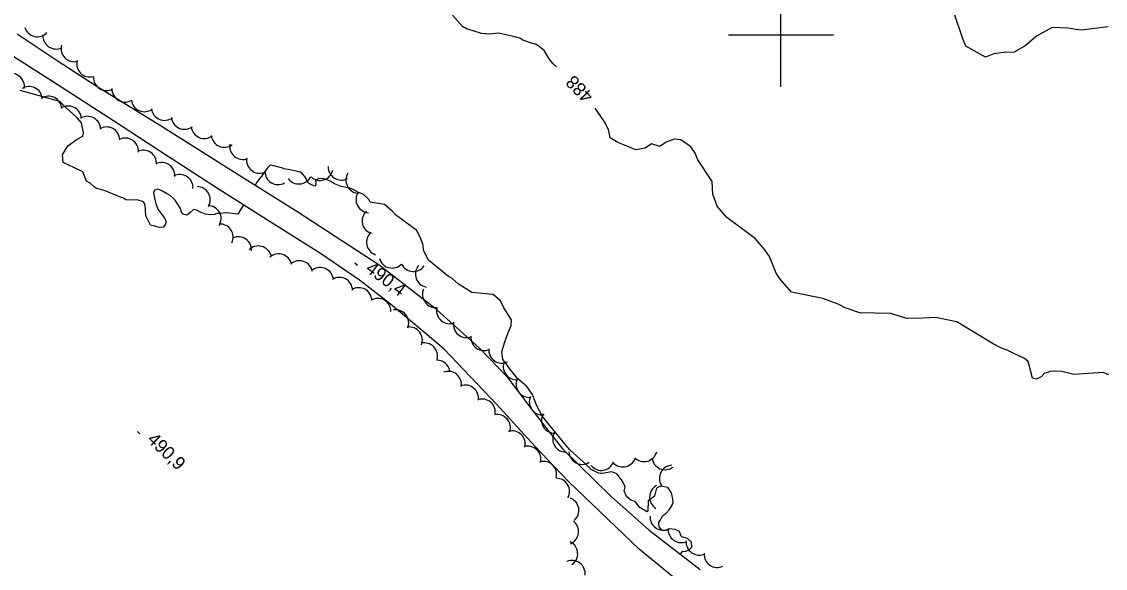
# Model space of a CAD drawing. Extents: x 642515 to 647219, y 6080136 to 6084356.
# Drawn here: x 643026.5 to 643274.3, y 6082078.2 to 6082203 of the extents above; entities that cross this region are included whole.
import ezdxf

# ---------------------------------------------------------------- set-up
doc = ezdxf.new("R2010")
doc.units = 0
for name, color, linetype in [('Level 1', 7, 'Continuous'), ('Level 2', 7, 'Continuous'), ('Level 21', 7, 'Continuous'), ('Level 3', 7, 'Continuous'), ('Level 44', 7, 'Continuous'), ('Level 61', 7, 'Continuous')]:
    doc.layers.add(name, color=color, linetype=linetype)

msp = doc.modelspace()

# ---------------------------------------------------------------- linework, layer by layer
at = {"layer": 'Level 1'}
for points in [[(643063.32, 6082159.04), (643063.05, 6082159.59), (643062.79, 6082160.5), (643062.3, 6082161.23), (643061.67, 6082162.24), (643060.73, 6082163.16), (643059.65, 6082163.82), (643058.73, 6082164.33), (643057.82, 6082164.76), (643056.94, 6082164.54), (643056.69, 6082164), (643056.82, 6082163.21), (643056.95, 6082162.41), (643057.25, 6082161.54), (643057.41, 6082160.86), (643057.65, 6082160.19), (643059.31, 6082158.11), (643059.6, 6082157.33), (643059.32, 6082156.66), (643058.91, 6082156.12), (643057.95, 6082156.06), (643056.97, 6082156.32), (643056.03, 6082156.55), (643054.93, 6082158.66), (643054.89, 6082159.99), (643054.77, 6082161.23), (643054.37, 6082161.89), (643052.93, 6082162.33), (643051.37, 6082162.28), (643050.36, 6082162.34), (643049.81, 6082162.75), (643048.94, 6082163.06), (643048.2, 6082163.34), (643046.55, 6082164.05), (643045.64, 6082164.4), (643044.57, 6082164.74), (643043.63, 6082164.96), (643043.17, 6082165.22), (643042.23, 6082166.13), (643041.39, 6082166.64), (643040.5, 6082168.73), (643038.59, 6082169.66), (643036.02, 6082170.88), (643035.91, 6082172.65), (643037.07, 6082174.65), (643039.23, 6082176.23), (643040.56, 6082176.87), (643040.67, 6082177.68), (643040.21, 6082179.91), (643039.17, 6082181.14), (643038.23, 6082181.97), (643036.62, 6082183.41), (643035.24, 6082184.78), (643026.23, 6082187.31)], [(643172.61, 6082096.95), (643171.71, 6082096.45), (643171.18, 6082094.65), (643170.49, 6082094.04), (643169.8, 6082093.6), (643169.7, 6082091.25), (643169.51, 6082091.04), (643167.88, 6082092.03), (643166.83, 6082093.42), (643165.84, 6082093.76), (643164.79, 6082094.55), (643164.3, 6082095.89), (643164.53, 6082096.75), (643163.93, 6082098.04), (643162.62, 6082099.74), (643161.5, 6082100.19), (643159.27, 6082099.82), (643158.95, 6082099.8), (643158.38, 6082099.93), (643156.76, 6082100.76), (643155.69, 6082101.78), (643154.11, 6082103.18), (643151.89, 6082105.22), (643150.37, 6082107.03), (643145.59, 6082112.87), (643144.22, 6082115.45), (643143.34, 6082117.89), (643142.03, 6082119.67), (643139.9, 6082121.56), (643138.07, 6082123.78), (643137.27, 6082124.95), (643136.57, 6082125.87), (643136.3, 6082127.63), (643136.9, 6082129.68), (643137.8, 6082132.07), (643138.43, 6082133.64), (643138.51, 6082134.93), (643136.81, 6082137.65), (643135.98, 6082139.3), (643134.37, 6082140.73), (643129.43, 6082141.16), (643126.33, 6082143.16), (643124.97, 6082144.36), (643124.14, 6082144.8), (643119.56, 6082148.56), (643118.47, 6082150.59), (643118.28, 6082152.27), (643117.81, 6082153.45), (643116.88, 6082155.33), (643111.99, 6082158.91), (643111.3, 6082159.67), (643109.52, 6082161.26), (643106.18, 6082161.78), (643105.9, 6082162.41), (643104.58, 6082163.66), (643103.55, 6082164.05), (643102.47, 6082164.63), (643101.56, 6082164.98), (643100.74, 6082165.17), (643099.6, 6082165.42), (643098.04, 6082165.98), (643097.24, 6082166.53), (643096.41, 6082166.89), (643095.59, 6082167.16), (643094.45, 6082167.25), (643093.71, 6082166.85), (643093.79, 6082166.33), (643093.82, 6082165.77), (643093.6, 6082165.43), (643092.82, 6082165.75), (643092.15, 6082166.19), (643091.48, 6082167.24), (643091.47, 6082167.4), (643090.77, 6082168.32), (643090.18, 6082168.69), (643089.57, 6082168.78), (643087.53, 6082169.3), (643086.43, 6082169.44), (643086.22, 6082169.55), (643084.17, 6082170.15), (643083.32, 6082170.3), (643082.79, 6082169.7), (643082.12, 6082168.78), (643081.46, 6082167.85), (643081.12, 6082167.47), (643080.97, 6082167.3), (643080.3, 6082166.37), (643079.91, 6082165.71)], [(643077.22, 6082161.19), (643075.96, 6082159.06), (643073.44, 6082159.4), (643071.6, 6082159.21), (643071.16, 6082159.22), (643070.57, 6082158.98), (643069.61, 6082158.93), (643068.47, 6082159.1), (643068.31, 6082159.17), (643067.56, 6082159.45), (643066.52, 6082159.99), (643065.79, 6082160.11), (643064.99, 6082159.38), (643064.34, 6082158.82), (643063.32, 6082159.04)], [(643177.2, 6082081.32), (643177.19, 6082081.42), (643177.67, 6082082.06), (643178.24, 6082082.01), (643179.18, 6082082.39), (643179.74, 6082083.03), (643179.64, 6082084.11), (643178.78, 6082084.94), (643177.47, 6082085.35), (643177.34, 6082085.54), (643176.95, 6082086.57), (643175.92, 6082087.03), (643174.62, 6082087.19), (643173.92, 6082086.83), (643172.91, 6082086.89), (643172.3, 6082087.66), (643172.24, 6082088.62), (643172.41, 6082089), (643173.1, 6082090.21), (643173.84, 6082090.69), (643174.63, 6082091.59), (643175.36, 6082092.76), (643175.35, 6082092.84), (643175.45, 6082093.21), (643175.44, 6082094.05), (643175.12, 6082095.4), (643174.28, 6082096.6), (643172.61, 6082096.95)]]:
    msp.add_lwpolyline(points, dxfattribs=at)
at = {"layer": 'Level 2'}
for points in [[(643148.85, 6082192.71), (643148.06, 6082193.41), (643147.1, 6082194.57), (643146.01, 6082196.44), (643144.83, 6082197.34), (643143.99, 6082197.93), (643143.58, 6082197.99), (643141.11, 6082198.81), (643140.44, 6082199.26), (643138.97, 6082199.65), (643135.53, 6082200.42), (643133.53, 6082200.22), (643131.67, 6082200.35), (643129.78, 6082200.96), (643128.22, 6082201.44), (643127.3, 6082201.95), (643125.04, 6082204.56)], [(643274.91, 6082201.88), (643271.38, 6082201.38), (643268.65, 6082201.07), (643265.72, 6082201.56), (643262.15, 6082201.7), (643258.55, 6082199.74), (643255.93, 6082197.52), (643253.43, 6082196.11), (643251.17, 6082195.99), (643248.76, 6082195.7), (643246.87, 6082194.96), (643242.36, 6082197.45), (643241.61, 6082199.34), (643239.85, 6082204.53)], [(643213.18, 6082138.53), (643209.72, 6082139.78), (643202.53, 6082141.28), (643199.94, 6082144.2), (643199.04, 6082145.6), (643197.52, 6082149.38), (643196.46, 6082150.93), (643194.2, 6082153.54), (643190.15, 6082156.53), (643187.78, 6082158.32), (643185.52, 6082160.93), (643184.55, 6082163.62), (643184.37, 6082166.51), (643181.16, 6082171.49), (643180.51, 6082172.98), (643179.53, 6082174.46), (643177.26, 6082176.02), (643175.72, 6082176.17), (643173.9, 6082175.5), (643172.43, 6082174.52), (643170.54, 6082175.14), (643169.07, 6082174.16), (643166.92, 6082173.79), (643164.35, 6082174.85), (643162.87, 6082175.41), (643161.11, 6082176.51), (643160.67, 6082178.42), (643159.76, 6082180.14), (643157.68, 6082183.31)], [(643275.09, 6082122.34), (643273.76, 6082122.9), (643267.1, 6082122.45), (643264.32, 6082123.09), (643262.62, 6082123.23), (643261.58, 6082123.09), (643261.11, 6082122.9), (643260.39, 6082122.78), (643259.64, 6082121.93), (643258.55, 6082121.38), (643257.65, 6082121.57), (643256.61, 6082125.38), (643255.84, 6082126.06), (643254.68, 6082126.63), (643252.77, 6082127.57), (643252.02, 6082127.93), (643250.54, 6082128.49), (643248.63, 6082129.42), (643247.87, 6082129.94), (643240.34, 6082134.5), (643235.44, 6082135.5), (643232.55, 6082135.32), (643228.85, 6082135.26), (643225.24, 6082136.34), (643221.69, 6082136.45), (643218.13, 6082136.56), (643214.84, 6082137.66), (643213.18, 6082138.53)]]:
    msp.add_lwpolyline(points, dxfattribs=at)
at = {"layer": 'Level 21'}
for points in [[(643175.36, 6082076.3), (643167.69, 6082082.55), (643151.53, 6082097.98), (643143.84, 6082106.08), (643135.08, 6082115.64), (643123.17, 6082128.23), (643115.92, 6082134.34), (643110.83, 6082138.54), (643103.74, 6082143.98), (643094.84, 6082150.11), (643082.74, 6082157.71), (643071.11, 6082165.05), (643059.45, 6082172.63), (643047.51, 6082180.4), (643033.59, 6082189.37), (643018.39, 6082199.03)], [(643025.49, 6082200.3), (643034.64, 6082194.18), (643043.61, 6082188.36), (643058.08, 6082179.5), (643074.33, 6082169.21), (643089.65, 6082159.6), (643108.26, 6082147.53), (643120.68, 6082137.91), (643131.24, 6082128.42), (643137.42, 6082122.04), (643143.64, 6082113.81), (643150.18, 6082105.44), (643161.4, 6082094.46), (643170, 6082086.85), (643181.65, 6082077.9)]]:
    msp.add_lwpolyline(points, dxfattribs=at)
at = {"layer": 'Level 3'}
for p, q in [((643102.69, 6082147.93), (643103.33, 6082147.44)), ((643053.01, 6082109.42), (643053.58, 6082108.86))]:
    msp.add_line(p, q, dxfattribs=at)
at = {"layer": 'Level 44'}
for centre, start, end in [((643030.15, 6082202.6), 196.7475, 316.7254), ((643034.41, 6082199.8), 175.6176, 295.5955), ((643038.55, 6082196.91), 165.5796, 285.5575), ((643042.12, 6082193.41), 165.5796, 285.5575), ((643024.17, 6082188.23), 350.6988, 110.6767), ((643045.94, 6082190.32), 177.9481, 297.926), ((643028.24, 6082185.25), 3.496, 123.474), ((643032.72, 6082183.02), 3.496, 123.474), ((643050.18, 6082187.67), 177.9481, 297.926), ((643037.19, 6082180.78), 3.496, 123.474), ((643054.6, 6082185.48), 186.6658, 306.6437), ((643041.58, 6082178.43), 1.0007, 120.9786), ((643059.2, 6082183.5), 186.6658, 306.6437), ((643063.76, 6082181.45), 185.175, 305.1529), ((643045.96, 6082176), 1.0007, 120.9786), ((643068.3, 6082179.35), 186.2237, 306.2017), ((643050.23, 6082173.46), 356.185, 116.163), ((643072.87, 6082177.34), 186.2237, 306.2017), ((643054.38, 6082170.68), 356.185, 116.163), ((643077.09, 6082174.58), 170.7042, 290.6821), ((643080.96, 6082171.41), 170.7042, 290.6821), ((643058.53, 6082167.89), 356.185, 116.163), ((643085.16, 6082168.81), 179.4048, 299.3828), ((643094.75, 6082169.77), 226.9578, 346.9358), ((643099.6, 6082169.86), 178.536, 298.5139), ((643062.7, 6082165.13), 356.6135, 116.5915), ((643089.9, 6082168.96), 214.6527, 334.6307), ((643103.67, 6082166.84), 147.6287, 267.6066), ((643066.66, 6082162.37), 329.7159, 89.6939), ((643105.98, 6082162.41), 147.6287, 267.6066), ((643069.14, 6082158.02), 329.7159, 89.6939), ((643107.38, 6082157.56), 132.7666, 252.7446), ((643071.9, 6082153.83), 333.6771, 93.6551), ((643076.09, 6082150.91), 355.5719, 115.5498), ((643108.39, 6082152.65), 130.8305, 250.8085), ((643080.66, 6082148.81), 15.3844, 135.3624), ((643085.3, 6082147), 11.7859, 131.7639), ((643111.23, 6082149.76), 195.523, 315.501), ((643090.05, 6082145.44), 11.7859, 131.7639), ((643094.8, 6082143.87), 11.7859, 131.7639), ((643116.1, 6082148.96), 205.672, 325.65), ((643119.56, 6082145.37), 138.9995, 258.9775), ((643099.19, 6082141.62), 1.8428, 121.8207), ((643103.6, 6082139.26), 1.8428, 121.8207), ((643121.17, 6082140.74), 156.5556, 276.5335), ((643107.97, 6082136.84), 0.2662, 120.2441), ((643112.03, 6082134.21), 338.6003, 98.5782), ((643124.38, 6082137.04), 170.7177, 290.6956), ((643128.25, 6082133.88), 170.7177, 290.6956), ((643115.15, 6082130.3), 338.6003, 98.5782), ((643118.61, 6082126.66), 344.6031, 104.5811), ((643132.24, 6082130.91), 174.9507, 294.9287), ((643136.33, 6082128.03), 174.9507, 294.9287), ((643121.51, 6082122.7), 10.8443, 91.8802), ((643139.64, 6082124.23), 155.3861, 275.364), ((643124.09, 6082120.14), 351.25, 111.2279), ((643127.99, 6082117.01), 351.25, 111.2279), ((643142.58, 6082120.2), 157.1973, 277.1752), ((643131.83, 6082113.83), 349.2013, 109.1792), ((643145.6, 6082116.22), 157.1973, 277.1752), ((643135.29, 6082110.29), 341.4823, 101.4603), ((643148.37, 6082112.02), 150.934, 270.9119), ((643138.66, 6082106.56), 345.9145, 105.8925), ((643150.94, 6082107.73), 150.934, 270.9119), ((643142.25, 6082103.08), 345.9145, 105.8925), ((643154.66, 6082104.91), 182.6111, 302.589), ((643168.82, 6082105.53), 224.6743, 344.6523), ((643145.84, 6082099.6), 345.9145, 105.8925), ((643159.06, 6082103.53), 219.2712, 339.2491), ((643163.99, 6082104.33), 219.2712, 339.2491), ((643173.63, 6082103.69), 187.3119, 307.2899), ((643175.33, 6082098.72), 92.5132, 212.4912), ((643148.8, 6082095.72), 331.5161, 91.4941), ((643173.08, 6082094.41), 118.527, 238.505), ((643150.93, 6082091.39), 310.1334, 70.1113), ((643173.2, 6082089.86), 175.4495, 295.4275), ((643150.87, 6082086.54), 292.718, 52.696), ((643177.32, 6082087.02), 175.4495, 295.4275), ((643181.43, 6082084.19), 175.4495, 295.4275), ((643150.66, 6082081.5), 304.4281, 64.406), ((643152.36, 6082076.96), 353.09, 113.0679), ((643185.56, 6082081.36), 175.7152, 295.6932)]:
    msp.add_arc(centre, 3, start, end, dxfattribs=at)
at = {"layer": 'Level 61'}
for p, q in [((643200, 6082212.16), (643200, 6082188.16)), ((643212.16, 6082200), (643188.16, 6082200))]:
    msp.add_line(p, q, dxfattribs=at)

# ---------------------------------------------------------------- texts
at = {"layer": 'Level 2'}
msp.add_text('488', height=3, rotation=134.2314, dxfattribs=at).set_placement((643157.46, 6082186.25))
at = {"layer": 'Level 3'}
for s, rotation, p in [('490,4', 322.9158, (643104.96, 6082146.16)), ('490,9', 315.59, (643055.04, 6082107.37))]:
    msp.add_text(s, height=3, rotation=rotation, dxfattribs=at).set_placement(p)

doc.saveas('drawing.dxf')
